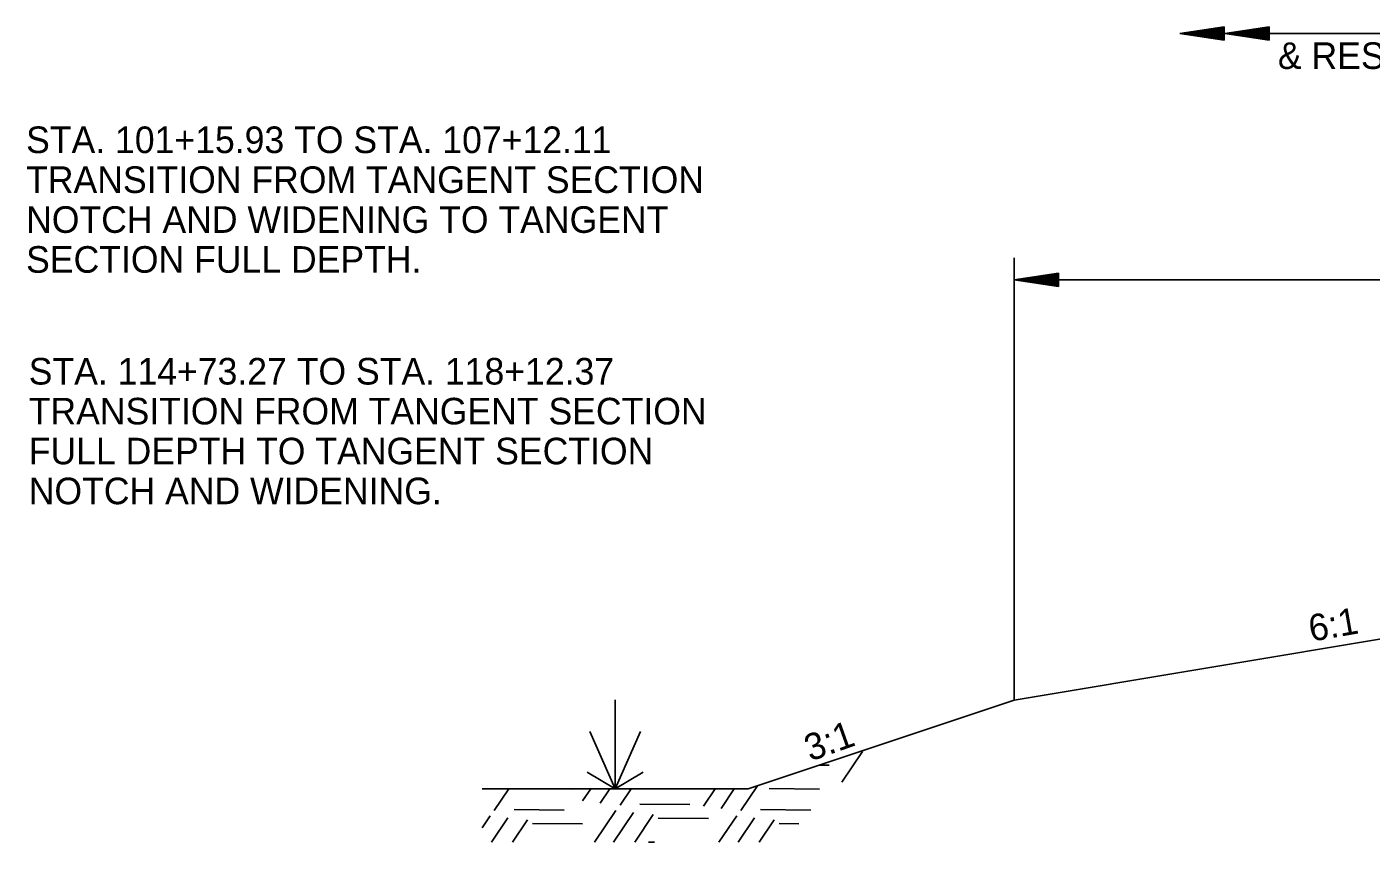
# Model space of a CAD drawing. Extents: x -900 to 15312, y 1857 to 2945.
# Drawn here: x 1608.5 to 1911.7, y 2084.4 to 2268.3 of the extents above; entities that cross this region are included whole.
import ezdxf

# ---------------------------------------------------------------- set-up
doc = ezdxf.new("R2010")
doc.units = 0
for name, color, linetype in [('R_Annotation', 7, 'Continuous'), ('R_Dimension', 7, 'Continuous'), ('R_Draft', 7, 'Continuous')]:
    doc.layers.add(name, color=color, linetype=linetype)

msp = doc.modelspace()

# ---------------------------------------------------------------- linework, layer by layer
at = {"layer": 'R_Annotation'}
for p, q in [((1991.17, 2143.08), (1831.17, 2116.41)), ((1831.17, 2116.41), (1771.17, 2096.41)), ((1771.17, 2096.41), (1711.17, 2096.41))]:
    msp.add_line(p, q, dxfattribs=at)
at = {"layer": 'R_Dimension'}
for p, q in [((1878.55, 2268.31), (1868.55, 2266.81)), ((1878.55, 2268.06), (1870.22, 2266.81)), ((1878.55, 2267.8), (1871.94, 2266.81)), ((1878.55, 2265.31), (1878.55, 2268.31)), ((1888.72, 2268.31), (1878.72, 2266.81)), ((1888.72, 2268.06), (1880.39, 2266.81)), ((1888.72, 2267.8), (1882.11, 2266.81)), ((1888.72, 2265.31), (1888.72, 2268.31)), ((1868.55, 2266.81), (2309.56, 2266.81)), ((1878.55, 2265.31), (1868.55, 2266.81)), ((1878.55, 2265.56), (1870.22, 2266.81)), ((1878.55, 2265.81), (1871.94, 2266.81)), ((1878.55, 2267.55), (1873.61, 2266.81)), ((1878.55, 2266.06), (1873.61, 2266.81)), ((1878.55, 2267.3), (1875.3, 2266.81)), ((1878.55, 2266.32), (1875.3, 2266.81)), ((1878.55, 2267.04), (1876.97, 2266.81)), ((1878.55, 2266.57), (1876.97, 2266.81)), ((1888.72, 2265.31), (1878.72, 2266.81)), ((1888.72, 2265.56), (1880.39, 2266.81)), ((1888.72, 2265.81), (1882.11, 2266.81)), ((1888.72, 2267.55), (1883.77, 2266.81)), ((1888.72, 2266.06), (1883.77, 2266.81)), ((1888.72, 2267.3), (1885.47, 2266.81)), ((1888.72, 2266.32), (1885.47, 2266.81)), ((1888.72, 2267.04), (1887.14, 2266.81)), ((1888.72, 2266.57), (1887.14, 2266.81)), ((1831.17, 2116.41), (1831.17, 2216.21)), ((1841.17, 2212.71), (1831.17, 2211.21)), ((1841.17, 2209.71), (1831.17, 2211.21)), ((1831.17, 2211.21), (2031.18, 2211.21)), ((1841.17, 2212.46), (1832.84, 2211.21)), ((1841.17, 2209.96), (1832.84, 2211.21)), ((1841.17, 2212.21), (1834.56, 2211.21)), ((1841.17, 2210.22), (1834.56, 2211.21)), ((1841.17, 2211.96), (1836.23, 2211.21)), ((1841.17, 2210.47), (1836.23, 2211.21)), ((1841.17, 2211.7), (1837.92, 2211.21)), ((1841.17, 2210.72), (1837.92, 2211.21)), ((1841.17, 2211.45), (1839.59, 2211.21)), ((1841.17, 2210.98), (1839.59, 2211.21)), ((1841.17, 2212.71), (1841.17, 2209.71)), ((1792.31, 2097.89), (1796.98, 2104.8)), ((1787.22, 2101.76), (1789.47, 2101.74)), ((1713.92, 2091.54), (1717.2, 2096.41)), ((1725.89, 2096.41), (1731.62, 2096.36)), ((1733.85, 2093.67), (1735.7, 2096.41)), ((1737.84, 2093.21), (1740, 2096.41)), ((1742.29, 2092.75), (1744.76, 2096.41)), ((1761.1, 2092.47), (1763.76, 2096.41)), ((1765.09, 2092.01), (1768.06, 2096.41)), ((1769.54, 2091.54), (1773.3, 2097.12)), ((1775.94, 2096.46), (1787.24, 2096.36)), ((1746.73, 2092.93), (1758.04, 2092.84)), ((1711.17, 2087.64), (1712.99, 2090.34)), ((1713.28, 2084.39), (1716.98, 2089.87)), ((1718.04, 2084.39), (1721.43, 2089.41)), ((1718.37, 2091.73), (1729.68, 2091.63)), ((1736.53, 2084.39), (1741.36, 2091.54)), ((1740.83, 2084.39), (1745.34, 2091.08)), ((1745.59, 2084.39), (1749.79, 2090.61)), ((1750.91, 2089.78), (1762.22, 2089.69)), ((1764.6, 2084.39), (1768.61, 2090.34)), ((1768.9, 2084.39), (1772.6, 2089.87)), ((1773.66, 2084.39), (1777.05, 2089.41)), ((1773.99, 2091.73), (1785.3, 2091.63)), ((1722.54, 2088.57), (1733.85, 2088.48)), ((1778.16, 2088.57), (1782.59, 2088.54)), ((1748.68, 2084.4), (1750.03, 2084.39))]:
    msp.add_line(p, q, dxfattribs=at)
at = {"layer": 'R_Draft'}
for q in [(1741.17, 2116.5), (1735.48, 2109.34), (1746.87, 2109.34), (1734.88, 2100.2), (1747.47, 2100.2)]:
    msp.add_line((1741.17, 2096.41), q, dxfattribs=at)

# ---------------------------------------------------------------- texts
at = {"layer": 'R_Annotation'}
for s, p in [('& RESHAPE CLEAR ZONE', (1890.66, 2258.82)), ('STA. 101+15.93 TO STA. 107+12.11', (1608.33, 2239.84)), ('TRANSITION FROM TANGENT SECTION', (1608.33, 2230.84)), ('NOTCH AND WIDENING TO TANGENT ', (1608.33, 2221.84)), ('SECTION FULL DEPTH. ', (1608.33, 2212.84)), ('STA. 114+73.27 TO STA. 118+12.37', (1608.92, 2187.62)), ('TRANSITION FROM TANGENT SECTION', (1608.92, 2178.62)), ('FULL DEPTH TO TANGENT SECTION ', (1608.92, 2169.62)), ('NOTCH AND WIDENING.', (1608.92, 2160.62))]:
    msp.add_text(s, height=6, dxfattribs=at).set_placement(p)
for s, rotation, p in [('6:1', 9.9734, (1898.15, 2129.59)), ('3:1', 19.6286, (1785.19, 2102.55))]:
    msp.add_text(s, height=6, rotation=rotation, dxfattribs=at).set_placement(p)

doc.saveas('drawing.dxf')
